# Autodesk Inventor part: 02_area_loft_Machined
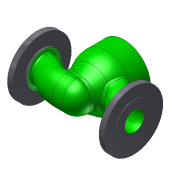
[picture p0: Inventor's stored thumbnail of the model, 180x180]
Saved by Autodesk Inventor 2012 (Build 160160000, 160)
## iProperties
Created: 2007-03
Part Number: 02_area_loft_Machined
Document SubType Name: Modeling
Designer: 43011
Mass: 8830.27 g
Surface Area: 1996.44 cm^2
Volume: 1124.88 cm^3
Density: 7.85 g/cm^3
Material: Steel
Author: 43011
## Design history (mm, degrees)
derived "02_area_loft_casting.ipt"
derived "02_are_loft_def_finished.ipt"
revolve "Revolution2" stored, may be unused: angle "d5" = 90 deg
mirror "Mirror1"
sketch "Sketch7"
  geometry: L1 (-182.013, 0)-(182.01, 0) reference; L2 (0, -113.6)-(0, 139.1) reference; L3 (-37, 103)-(0, 103); L4 (0, 103)-(0, 30); L5 (-37, 30)-(-37, 103); L6 (70, 103)-(-70, 103) reference; L7 (-37, 30)-(-35.468, 30); L8 (-35.468, 30)-(-35.468, 0.65); L9 (-35.468, 0.65)-(-27.75, 0.65); L10 (-27.75, 0.65)-(-27.75, -0.25); L11 (-27.75, -0.25)-(0, -0.25); 1 further point
  constraints: 16 end point, 4 perpendicular, 3 parallel, 2 point on line, 1 collinear, 1 horizontal
  dimensions: "d39" = 74 diameter of L5 L2; "d42" = 70.935 diameter of L8 L2; "d43" = 0.65 distance between parallel lines of L1 L9; "d45" = 55.5 diameter of L10 L2; "d46" = 0.25 distance between parallel lines of L11 L1
revolve "Revolution3" sketch "Sketch7" stored, may be unused: angle "d41" = 90 deg
node "Volumenkörper1"
node "Volumenkörpern"
node "Oberflächenkörpern"
tag "Bezeichnung2"
sketch "Sketch15"
  geometry: L1 (-37.013, 103)-(-37.013, 30); L2 (-37.013, 30)-(0, 30); L3 (70, 103)-(-70, 103) reference; L4 (-37.013, 103)-(0, 103); L5 (0, -121.184)-(0, 184.601) reference; L6 (-182.013, 0)-(182.01, 0) reference; L7 (0, 30)-(0, 103)
  constraints: 8 end point, 2 collinear, 1 parallel, 1 point on line
  dimensions: "d37" = 74.025 diameter of L1 L5; "d38" = 30 distance between parallel lines of L6 L2
sketch "Sketch20"
  geometry: L1 (-128, 77.5)-(-114, 77.5); L2 (-114, 77.5)-(-114, 45); L3 (-114, 45)-(-107, 45); L4 (-107, 45)-(-107, 100.638); L5 (-128, 77.5)-(-128, 48); L6 (-128, 48)-(-130, 48); L7 (-130, 48)-(-130, 0); L8 (0, -81.107)-(0, 145.351); L9 (-205.8, 0)-(205.8, 0); L10 (-130, 0)-(-152.983, 0)
  constraints: 20 end point
feature "DerivedBody::02_area_loft_casting.ipt" dims "d0" = 10
other parameters: "d4" = 90 deg
